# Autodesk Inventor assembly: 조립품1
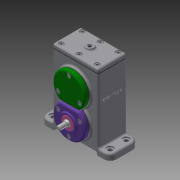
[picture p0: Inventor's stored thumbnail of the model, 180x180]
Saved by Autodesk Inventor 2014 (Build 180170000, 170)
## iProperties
Created: 2020-05
Part Number: 조립품1
Document SubType Name: Assembly
Designer: kh
Mass: 1076.75 g
Surface Area: 1575.48 cm^2
Volume: 384.079 cm^3
Density: 2.80345 g/cm^3
Author: kh
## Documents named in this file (24)
- C:\Users\kh\Desktop\600506V1059\조립품1.iam
- C:\Users\kh\Desktop\600506V1059\본체.ipt
- C:\Users\kh\Desktop\600506V1059\개스킷 A.ipt
- C:\Users\kh\Desktop\600506V1059\개스킷 B.ipt
- C:\Users\kh\Desktop\600506V1059\개스킷 C.ipt
- C:\Users\kh\Desktop\600506V1059\베어링 6001.ipt
- 베어링 6001.ipt
- C:\Users\kh\Desktop\600506V1059\베어링 6002.ipt
- 베어링 6002.ipt
- C:\Users\kh\Desktop\600506V1059\볼트 M4.ipt
- C:\Users\kh\Desktop\600506V1059\스퍼기어 A.ipt
- C:\Users\kh\Desktop\600506V1059\스퍼기어 B.ipt
- C:\Users\kh\Desktop\600506V1059\오일 실 10 20 7.ipt
- C:\Users\kh\Desktop\600506V1059\오일 실 12 22 7.ipt
- C:\Users\kh\Desktop\600506V1059\축 A.ipt
- C:\Users\kh\Desktop\600506V1059\축 B.ipt
- C:\Users\kh\Desktop\600506V1059\칼라.ipt
- C:\Users\kh\Desktop\600506V1059\커버 A.ipt
- C:\Users\kh\Desktop\600506V1059\커버 B.ipt
- C:\Users\kh\Desktop\600506V1059\커버 C.ipt
- C:\Users\kh\Desktop\600506V1059\커버 D.ipt
- C:\Users\kh\Desktop\600506V1059\커버 E.ipt
- C:\Users\kh\Desktop\600506V1059\키 4 x 4 x 12.ipt
- C:\Users\kh\Desktop\600506V1059\키 5 x 5 x 12.ipt
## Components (5 placed, 3 different names)
1. 개스킷 A:1
2. 개스킷 C:1
3. 개스킷 B:1
4. 개스킷 B:2
5. 개스킷 B:3
